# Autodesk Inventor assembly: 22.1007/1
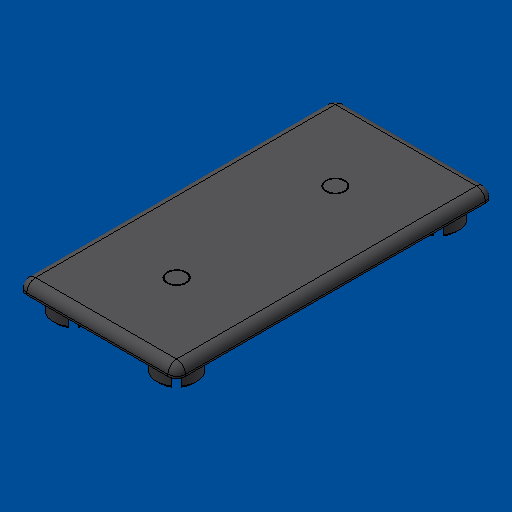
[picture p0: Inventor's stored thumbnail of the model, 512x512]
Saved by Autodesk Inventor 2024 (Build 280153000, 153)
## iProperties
Created: 2012-02
Part Number: 22.1007/1
Document SubType Name: Assembly
Designer: Administrator
Vendor: S
Description: END CAP 45X90 GRAY
Mass: 11.4345 g
Surface Area: 112.634 cm^2
Volume: 10.7873 cm^3
Density: 1.06 g/cm^3
Author: Administrator
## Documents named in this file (4)
- L:\INVENTOR LIBRARIES\PARTS LIBRARY\END CAPS\22.1007_1 END CAP 45x90  GRAY.iam
- 22.1007/1 END CAP 45x90  GRAY.iam
- L:\INVENTOR LIBRARIES\PARTS LIBRARY\END CAPS\SUBCOMPONENTS\22.1007_1 End Cap 45x90 Gray.ipt
- L:\INVENTOR LIBRARIES\PARTS LIBRARY\END CAPS\SUBCOMPONENTS\END CAP DOWEL GRAY.ipt
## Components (3 placed, 2 different names)
1. 22.1007_1 End Cap 45x90 Gray:1 — Mate:1, Mate:2, Flush:1, Flush:2
2. END CAP DOWEL GRAY:1 — Mate:1, Flush:2
3. END CAP DOWEL GRAY:2 — Mate:2, Flush:1
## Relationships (4: Mate 2, Flush 2)
- Mate:1: 22.1007_1 End Cap 45x90 Gray:1 ↔ END CAP DOWEL GRAY:1
- Mate:2: 22.1007_1 End Cap 45x90 Gray:1 ↔ END CAP DOWEL GRAY:2
- Flush:1: 22.1007_1 End Cap 45x90 Gray:1 ↔ END CAP DOWEL GRAY:2
- Flush:2: 22.1007_1 End Cap 45x90 Gray:1 ↔ END CAP DOWEL GRAY:1
